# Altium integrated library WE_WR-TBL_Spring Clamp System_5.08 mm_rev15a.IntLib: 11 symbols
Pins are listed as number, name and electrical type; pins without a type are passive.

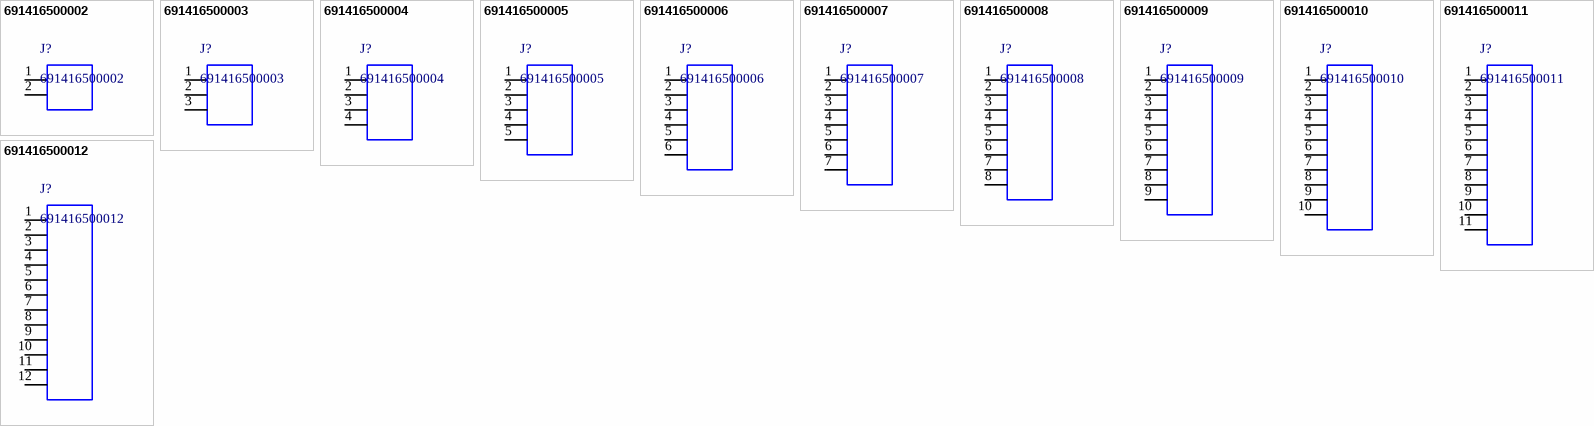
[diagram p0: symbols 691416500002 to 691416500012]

## 691416500002
designator J?
WR-TBL Vertical Cable Entry Screwless, Serie 4165 - 5.08 mm; Manufacturer: Wurth Elektronik; ComponentLink1 Description: Manufacturer; ComponentLink2 Description: Datasheet
footprint 691416500002 (Serie 4165 - 5.08 mm _ 2 pins)
pins: 1, 2

## 691416500003
designator J?
WR-TBL Vertical Cable Entry Screwless, Serie 4165 - 5.08 mm; Manufacturer: Wurth Elektronik; ComponentLink1 Description: Manufacturer; ComponentLink2 Description: Datasheet
footprint 691416500003 (Serie 4165 - 5.08 mm _ 3 pins)
pins: 1, 2, 3

## 691416500004
designator J?
WR-TBL Vertical Cable Entry Screwless, Serie 4165 - 5.08 mm; Manufacturer: Wurth Elektronik; ComponentLink1 Description: Manufacturer; ComponentLink2 Description: Datasheet
footprint 691416500004 (Serie 4165 - 5.08 mm _ 4 pins)
pins: 1, 2, 3, 4

## 691416500005
designator J?
WR-TBL Vertical Cable Entry Screwless, Serie 4165 - 5.08 mm; Manufacturer: Wurth Elektronik; ComponentLink1 Description: Manufacturer; ComponentLink2 Description: Datasheet
footprint 691416500005 (Serie 4165 - 5.08 mm _ 5 pins)
pins: 1, 2, 3, 4, 5

## 691416500006
designator J?
WR-TBL Vertical Cable Entry Screwless, Serie 4165 - 5.08 mm; Manufacturer: Wurth Elektronik; ComponentLink1 Description: Manufacturer; ComponentLink2 Description: Datasheet
footprint 691416500006 (Serie 4165 - 5.08 mm _ 6 pins)
pins: 1, 2, 3, 4, 5, 6

## 691416500007
designator J?
WR-TBL Vertical Cable Entry Screwless, Serie 4165 - 5.08 mm; Manufacturer: Wurth Elektronik; ComponentLink1 Description: Manufacturer; ComponentLink2 Description: Datasheet
footprint 691416500007 (Serie 4165 - 5.08 mm _ 7 pins)
pins: 1, 2, 3, 4, 5, 6, 7

## 691416500008
designator J?
WR-TBL Vertical Cable Entry Screwless, Serie 4165 - 5.08 mm; Manufacturer: Wurth Elektronik; ComponentLink1 Description: Manufacturer; ComponentLink2 Description: Datasheet
footprint 691416500008 (Serie 4165 - 5.08 mm _ 8 pins)
pins: 1, 2, 3, 4, 5, 6, 7, 8

## 691416500009
designator J?
WR-TBL Vertical Cable Entry Screwless, Serie 4165 - 5.08 mm; Manufacturer: Wurth Elektronik; ComponentLink1 Description: Manufacturer; ComponentLink2 Description: Datasheet
footprint 691416500009 (Serie 4165 - 5.08 mm _ 9 pins)
pins: 1, 2, 3, 4, 5, 6, 7, 8, 9

## 691416500010
designator J?
WR-TBL Vertical Cable Entry Screwless, Serie 4165 - 5.08 mm; Manufacturer: Wurth Elektronik; ComponentLink1 Description: Manufacturer; ComponentLink2 Description: Datasheet
footprint 691416500010 (Serie 4165 - 5.08 mm _ 10 pins)
pins: 1, 2, 3, 4, 5, 6, 7, 8, 9, 10

## 691416500011
designator J?
WR-TBL Vertical Cable Entry Screwless, Serie 4165 - 5.08 mm; Manufacturer: Wurth Elektronik; ComponentLink1 Description: Manufacturer; ComponentLink2 Description: Datasheet
footprint 691416500011 (Serie 4165 - 5.08 mm _ 11 pins)
pins: 1, 2, 3, 4, 5, 6, 7, 8, 9, 10, 11

## 691416500012
designator J?
WR-TBL Vertical Cable Entry Screwless, Serie 4165 - 5.08 mm; Manufacturer: Wurth Elektronik; ComponentLink1 Description: Manufacturer; ComponentLink2 Description: Datasheet
footprint 691416500012 (Serie 4165 - 5.08 mm _ 12 pins)
pins: 1, 2, 3, 4, 5, 6, 7, 8, 9, 10, 11, 12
